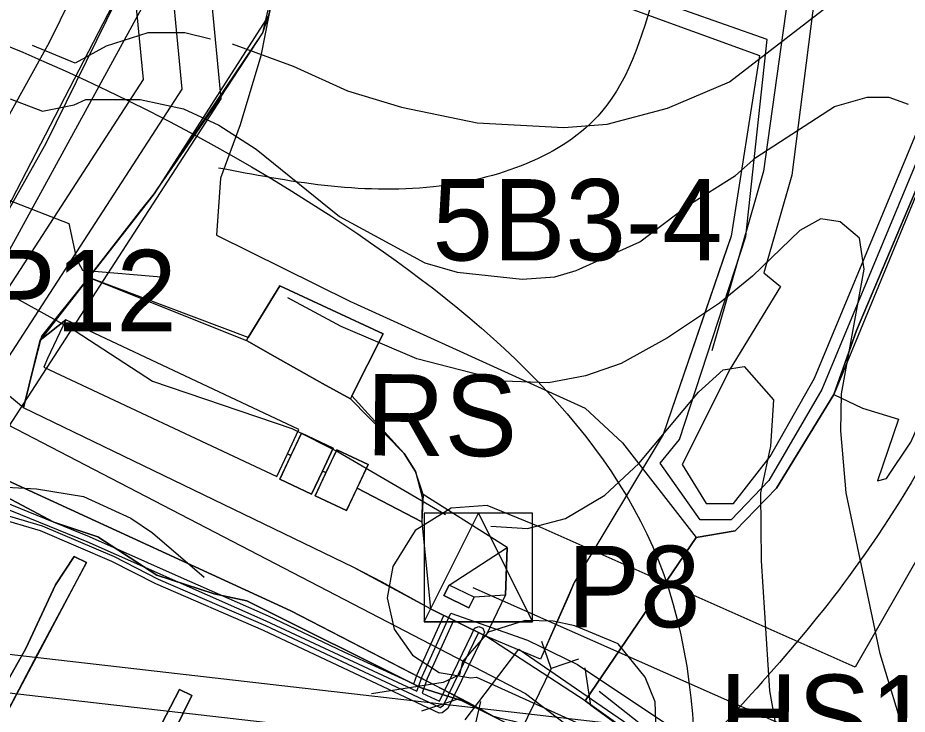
# Model space of a CAD drawing. Extents: x -684583 to -680383, y -1157874 to -1154904.
# Drawn here: x -683041.8 to -682877.8, y -1157026.8 to -1156898.5 of the extents above; entities that cross this region are included whole.
import ezdxf

# ---------------------------------------------------------------- set-up
doc = ezdxf.new("R2010")
doc.units = 0
for name, color, linetype in [('01_DOPRAVA', 7, 'Continuous'), ('01_OBVOD PÚ', 7, 'Continuous'), ('01_VRSTEVNICE', 7, 'Continuous'), ('02_KULTURY NÁVRH', 7, 'Continuous'), ('02_KULTURY STAV', 7, 'Continuous'), ('03_PC_NÁVRH', 7, 'Continuous'), ('03_PC_OBJEKTY_NÁVRH', 7, 'Continuous'), ('03_PC_OBJEKTY_STAV', 7, 'Continuous'), ('03_PC_STAV', 7, 'Continuous'), ('04_ZPF_OP_ORGAN', 7, 'Continuous'), ('06_BIOGEOGRAFIE', 7, 'Continuous'), ('06_ÚSES_IP', 7, 'Continuous'), ('07_ELEKTRO', 7, 'Continuous'), ('07_OCH_P A POPISY TI', 7, 'Continuous'), ('07_PLYNOVOD', 7, 'Continuous'), ('07_VODOVOD', 7, 'Continuous')]:
    doc.layers.add(name, color=color, linetype=linetype)

msp = doc.modelspace()

# ---------------------------------------------------------------- linework, layer by layer
at = {"layer": '01_DOPRAVA'}
msp.add_lwpolyline([(-683054.51, -1157758.92), (-683045.66, -1157702.14), (-683033.32, -1157625.99), (-683033.32, -1157571.3), (-683045.07, -1157508.09), (-683105.62, -1157372.25), (-683148.82, -1157294.04), (-683163.81, -1157254.05), (-683168.81, -1157196.71), (-683165.28, -1157159.67), (-683135.89, -1157075.28), (-683079.46, -1156981.49), (-683035.96, -1156902.98), (-682993.94, -1156817.72), (-682972.78, -1156716.87), (-682952.5, -1156631.31), (-682921.05, -1156497.23), (-682883.43, -1156372.57), (-682870.79, -1156344.34), (-682802.61, -1156200.56), (-682782.62, -1156147.93)], dxfattribs=at)
at = {"layer": '01_OBVOD PÚ'}
for points in [[(-682989.36, -1156869.91), (-682942.73, -1156891.65), (-682905.01, -1156905.43), (-682910.21, -1156938.74), (-682911.04, -1156940.97), (-682922.78, -1156975.26), (-682939.17, -1157002.56), (-682940.26, -1157005.08), (-682945.41, -1157016.69), (-682955.51, -1157012.45), (-682965.71, -1157007.37), (-682974.58, -1157002.46), (-682979.82, -1156999.75), (-683040.73, -1156970.35), (-683038.56, -1156961.55), (-683037.65, -1156957.9), (-683028.68, -1156946.32), (-683018.91, -1156933.75), (-683016.64, -1156930.91), (-682996.6, -1156901.27), (-682995.5, -1156898)], [(-682989.36, -1156869.91), (-682942.73, -1156891.65), (-682905.01, -1156905.43), (-682910.21, -1156938.74), (-682922.78, -1156975.26), (-682939.17, -1157002.56), (-682945.41, -1157016.69), (-682955.51, -1157012.45), (-682965.71, -1157007.37), (-682974.58, -1157002.46), (-682979.82, -1156999.75), (-683040.73, -1156970.35), (-683037.34, -1156957.14), (-683028.68, -1156946.32), (-683018.91, -1156933.75), (-683016.64, -1156930.91), (-683005.44, -1156914.73), (-682996.6, -1156901.27)]]:
    msp.add_lwpolyline(points, close=True, dxfattribs=at)
at = {"layer": '01_VRSTEVNICE'}
for points in [[(-683002.28, -1156903.26), (-682991.01, -1156907.4), (-682981.02, -1156911.96), (-682971.04, -1156914.96), (-682957.06, -1156917.81), (-682941.08, -1156918.67), (-682933.09, -1156918.1), (-682921.97, -1156915.1), (-682910.56, -1156910.25), (-682892.58, -1156896.42)], [(-683006.27, -1156902.41), (-683010.98, -1156901.27), (-683017.83, -1156901.27), (-683025.53, -1156903.69), (-683031.23, -1156906.83), (-683039.08, -1156903.55)], [(-683043.21, -1156913.39), (-683037.22, -1156915.67), (-683031.38, -1156914.53), (-683029.24, -1156913.53), (-683019.25, -1156913.53), (-683011.26, -1156915.25), (-683004.7, -1156918.24), (-682997.85, -1156922.66), (-682982.45, -1156935.07), (-682966.76, -1156943.63), (-682960.77, -1156945.34), (-682948.79, -1156946.63), (-682942.79, -1156946.2), (-682938.8, -1156945.06), (-682927.1, -1156939.78), (-682918.26, -1156933.08), (-682909.42, -1156927.51), (-682905.71, -1156924.23), (-682891.16, -1156914.82), (-682885.17, -1156913.11), (-682881.17, -1156913.11), (-682877.6, -1156914.39)], [(-683053.49, -1156928.23), (-683032.37, -1156936.36), (-683030.95, -1156942.92), (-683029.88, -1156944.95), (-683013.97, -1156946.34)], [(-682877.89, -1157031.64), (-682882.74, -1157015.67), (-682889.02, -1156986), (-682890.01, -1156974.59), (-682889.87, -1156967.74), (-682885.74, -1156944.77), (-682886.59, -1156939.07), (-682890.16, -1156936.07), (-682893.72, -1156935.5), (-682897.58, -1156937.64), (-682906.28, -1156946.06), (-682912.41, -1156951.05), (-682921.97, -1156957.47), (-682930.53, -1156962.18), (-682937.09, -1156964.46), (-682943.93, -1156965.74), (-682952.21, -1156965.46), (-682968.18, -1156961.32), (-682982.16, -1156955.33), (-682992.01, -1156950.05)], [(-683120.37, -1156963.62), (-683111.97, -1156967.03), (-683096.56, -1156967.45), (-683086.86, -1156965.31), (-683079.88, -1156959.75), (-683070.32, -1156948.34), (-683065.75, -1156940.92), (-683060.47, -1156940.92), (-683052.63, -1156944.34), (-683031.23, -1156956.18), (-683016.97, -1156965.46), (-682991.29, -1156974.16), (-682982.73, -1156978.44), (-682962.91, -1156989.99)], [(-682954.57, -1156992.15), (-682947.79, -1156992.56), (-682940.8, -1156990.71), (-682933.52, -1156986.42), (-682927.25, -1156980.58), (-682916.26, -1156967.45), (-682911.7, -1156963.32), (-682907.85, -1156962.75), (-682902.43, -1156968.88), (-682903, -1156977.44), (-682904.85, -1156986), (-682904.71, -1156998.55), (-682903.14, -1157022.51), (-682901, -1157034.5), (-682898.57, -1157042.48), (-682895.15, -1157050.47), (-682887.45, -1157062.46), (-682874.9, -1157079), (-682872.76, -1157083.57), (-682871.9, -1157087.84), (-682870.76, -1157126.36), (-682866.48, -1157156.31), (-682866.48, -1157169.15), (-682867.48, -1157177.43)], [(-683085.58, -1157018.81), (-683075.45, -1157007.39), (-683069.89, -1156996.27), (-683065.47, -1156989.99), (-683056.34, -1156986.42), (-683048.35, -1156984.71), (-683038.36, -1156985.28), (-683029.66, -1156986.71), (-683020.96, -1156990.7), (-683016.95, -1156993.39), (-683007.41, -1157001.54)], [(-682933.95, -1157049.62), (-682930.38, -1157043.48), (-682925.82, -1157038.21), (-682923.96, -1157033.64), (-682924.25, -1157024.51), (-682926.1, -1157019.95), (-682931.1, -1157013.81), (-682939.08, -1157010.53), (-682943.08, -1157009.68), (-682948.21, -1157009.53), (-682955.06, -1157011.67), (-682959.77, -1157017.09), (-682960.34, -1157019.52), (-682963.33, -1157020.95), (-682976.6, -1157023.08)]]:
    msp.add_lwpolyline(points, dxfattribs=at)
at = {"layer": '02_KULTURY NÁVRH'}
msp.add_lwpolyline([(-682862.34, -1156892.05), (-682893.52, -1156966.98), (-682903.32, -1156983.72), (-682910.25, -1156990.96), (-682915.97, -1156990.96), (-682923.35, -1156980.55), (-682919.74, -1156976.18), (-682907.53, -1156938.79), (-682903.62, -1156902.45), (-682942.04, -1156888.88)], dxfattribs=at)
at = {"layer": '02_KULTURY STAV'}
for points in [[(-683056.67, -1156957.12), (-683048.23, -1156942.2), (-683019.85, -1156887.5), (-683003.71, -1156858.2), (-682991.86, -1156824.56), (-682984.3, -1156791.71), (-682974.99, -1156760.13), (-682970.35, -1156763.63), (-682967.31, -1156768.38), (-682966.01, -1156774.58), (-682965.79, -1156787.12), (-682967.42, -1156795.29), (-682979.58, -1156826.78), (-682989.36, -1156869.91), (-682995.5, -1156898), (-683016.64, -1156930.91), (-683028.68, -1156946.32), (-683037.65, -1156957.9), (-683040.73, -1156970.35)], [(-682851.1, -1156826.38), (-682850.89, -1156844.24), (-682854.34, -1156873.25), (-682860.06, -1156892.14), (-682887.1, -1156956.12), (-682891.29, -1156967.88), (-682886.04, -1156970.38), (-682879.39, -1156972.45), (-682883.26, -1156983.81), (-682881.57, -1156983.38), (-682877.08, -1156976.67), (-682874.97, -1156971.91), (-682871.59, -1156959.54), (-682861.19, -1156933.96), (-682850.61, -1156904.16), (-682845.6, -1156883.82), (-682841.06, -1156851.72), (-682842.39, -1156824.87)], [(-682995.5, -1156898), (-682996.97, -1156905.5), (-683000.81, -1156918.21), (-683004.43, -1156928.02), (-683005.16, -1156938.5), (-682980.59, -1156950.71), (-682937.18, -1156970.39), (-682930.27, -1156976.77), (-682916.7, -1156994.23), (-682937.14, -1157024.36), (-682955.51, -1157012.45), (-682951.84, -1157004.88), (-682951.52, -1156996.06), (-682967.04, -1156986.34), (-682968.47, -1156982.08), (-682970.56, -1156978.78), (-682980.18, -1156968.14), (-682974.44, -1156956.7), (-682993.49, -1156947.84), (-682999.31, -1156957.41), (-683028.68, -1156946.32), (-683016.64, -1156930.91), (-682996.6, -1156901.27)], [(-683037.65, -1156957.9), (-683028.68, -1156946.32), (-682999.62, -1156957.92), (-682994.31, -1156960.92), (-682985.63, -1156965.87), (-682980.45, -1156968.68), (-682970.56, -1156978.78), (-682968.47, -1156982.08), (-682967.21, -1156986.78), (-682967.3, -1156991.33), (-682979.24, -1156985.14), (-682977.18, -1156980.78), (-682982.98, -1156978.06), (-682984.97, -1156982.29), (-682985.6, -1156981.99), (-682983.61, -1156977.76), (-682989.5, -1156975), (-682991.45, -1156979.15), (-682992.08, -1156978.85), (-682989.96, -1156974.34), (-683032.95, -1156954.14)], [(-682993.49, -1156947.84), (-682974.44, -1156956.7), (-682980.18, -1156968.14), (-682980.45, -1156968.68), (-682985.63, -1156965.87), (-682994.31, -1156960.92), (-682999.62, -1156957.92), (-682999.31, -1156957.41)], [(-683040.73, -1156970.35), (-683037.65, -1156957.9), (-683032.95, -1156954.14), (-683036.3, -1156961.27), (-683037.02, -1156962.83), (-682994.04, -1156983.03), (-682992.08, -1156978.85), (-682991.45, -1156979.15), (-682993.49, -1156983.51), (-682987.61, -1156986.27), (-682985.6, -1156981.99), (-682984.97, -1156982.29), (-682986.98, -1156986.57), (-682981.19, -1156989.29), (-682979.24, -1156985.14), (-682967.3, -1156991.33), (-682965.71, -1157007.37), (-682979.82, -1156999.75)], [(-683032.95, -1156954.14), (-683036.3, -1156961.27), (-683037.02, -1156962.83), (-682994.04, -1156983.03), (-682992.08, -1156978.85), (-682989.96, -1156974.34)], [(-682989.5, -1156975), (-682983.61, -1156977.76), (-682985.6, -1156981.99), (-682987.61, -1156986.27), (-682993.49, -1156983.51)], [(-682982.98, -1156978.06), (-682977.18, -1156980.78), (-682981.19, -1156989.29), (-682986.98, -1156986.57)], [(-682965.71, -1157007.37), (-682955.51, -1157012.45), (-682951.84, -1157004.88), (-682957.64, -1157005.22), (-682958.64, -1157007.21), (-682963.22, -1157004.92), (-682962.23, -1157003.02), (-682951.52, -1156996.06), (-682967.04, -1156986.34), (-682967.3, -1156991.33)], [(-682962.23, -1157003.02), (-682951.52, -1156996.06), (-682951.84, -1157004.88), (-682957.64, -1157005.22)], [(-682962.23, -1157003.02), (-682963.22, -1157004.92), (-682958.64, -1157007.21), (-682957.64, -1157005.22)]]:
    msp.add_lwpolyline(points, close=True, dxfattribs=at)
for points in [[(-682833.65, -1156897.15), (-682841.03, -1156977.03), (-682844.53, -1157035.81), (-682845.68, -1157065.25), (-682845.68, -1157080.84), (-682844.82, -1157086.77), (-682850.09, -1157090.88), (-682883.77, -1157064.59), (-682922.79, -1157034.61), (-682937.14, -1157024.36), (-682916.7, -1156994.23), (-682909.51, -1156993.03), (-682901.87, -1156985.12), (-682891.29, -1156967.88), (-682886.04, -1156970.38), (-682879.39, -1156972.45), (-682883.26, -1156983.81), (-682881.57, -1156983.38), (-682877.08, -1156976.67), (-682874.97, -1156971.91), (-682871.59, -1156959.54), (-682861.19, -1156933.96), (-682850.61, -1156904.16), (-682845.6, -1156883.82)], [(-683019.85, -1156887.5), (-683036.61, -1156921.65), (-683048.23, -1156942.2)], [(-682995.5, -1156898), (-682996.97, -1156905.5), (-683000.81, -1156918.21), (-683004.43, -1156928.02), (-683005.16, -1156938.5), (-682980.59, -1156950.71), (-682937.18, -1156970.39), (-682930.27, -1156976.77), (-682916.7, -1156994.23), (-682909.51, -1156993.03), (-682901.87, -1156985.12), (-682891.29, -1156967.88), (-682887.1, -1156956.12), (-682860.06, -1156892.14)], [(-682792.27, -1157137.15), (-682805.97, -1157127.99), (-682850.09, -1157090.88), (-682883.77, -1157064.59), (-682922.79, -1157034.61), (-682937.14, -1157024.36), (-682955.51, -1157012.45), (-682965.71, -1157007.37), (-682979.82, -1156999.75), (-683040.73, -1156970.35), (-683056.67, -1156957.12)], [(-683061.29, -1156975.68), (-682991.45, -1157007.74), (-682963.23, -1157022.34), (-682954.24, -1157027.11), (-682953.02, -1157027.48), (-682950.58, -1157028.02), (-682947.67, -1157028.84), (-682927.83, -1157043.62), (-682886.7, -1157076.63), (-682857.33, -1157100.64), (-682818.58, -1157133.57), (-682799.92, -1157147.75), (-682755.75, -1157178.87)], [(-683045.99, -1156985.71), (-683035.15, -1156991.4), (-683027.03, -1156994.1), (-683016.15, -1157001.2), (-683005.6, -1157004.65), (-682999.55, -1157005.9), (-682967.43, -1157021.94), (-682958.63, -1157024.72), (-682991.45, -1157007.74), (-683061.29, -1156975.68)], [(-682954.24, -1157027.11), (-682958.63, -1157024.72), (-682967.43, -1157021.94), (-682999.55, -1157005.9), (-683005.6, -1157004.65), (-683016.15, -1157001.2), (-683027.03, -1156994.1), (-683035.15, -1156991.4), (-683045.99, -1156985.71)], [(-683044.54, -1157047.31), (-683026.78, -1157057.53), (-683003.8, -1157070.41), (-682984.94, -1157081.43), (-682973.97, -1157087.66), (-682964.52, -1157092.89), (-682963.47, -1157089.67), (-682983.84, -1157077.66), (-683002.59, -1157066.71), (-683024.71, -1157053.87), (-683009.7, -1157023.34), (-683011.98, -1157022.24), (-683027.52, -1157052.19), (-683050.51, -1157039.17), (-683029.14, -1156998.86), (-683031.38, -1156997.74), (-683034.85, -1157002.94), (-683040.33, -1157014.68), (-683053.23, -1157037.54)], [(-683053.23, -1157037.54), (-683040.33, -1157014.68), (-683034.85, -1157002.94), (-683031.38, -1156997.74), (-683029.14, -1156998.86), (-683038.16, -1157015.7), (-683050.51, -1157039.17)], [(-683027.52, -1157052.19), (-683011.98, -1157022.24), (-683009.7, -1157023.34), (-683024.71, -1157053.87)]]:
    msp.add_lwpolyline(points, dxfattribs=at)
at = {"layer": '03_PC_NÁVRH'}
msp.add_lwpolyline([(-682964.69, -1156716.62), (-682927.89, -1156728.11), (-682891.83, -1156757.49), (-682882.59, -1156768.47), (-682889.7, -1156822.56), (-682904.3, -1156926.72), (-682913.8, -1156959.84)], dxfattribs=at)
at = {"layer": '03_PC_OBJEKTY_NÁVRH'}
msp.add_lwpolyline([(-682675.61, -1157221.62), (-682750, -1157164.87), (-682805.97, -1157127.99), (-682886.81, -1157060.31), (-682934.61, -1157022.63)], dxfattribs=at)
at = {"layer": '03_PC_OBJEKTY_STAV'}
for points in [[(-682938.42, -1157016.68), (-682943.43, -1157018.4), (-682945.16, -1157013.39)], [(-682943.43, -1157018.4), (-682948.91, -1157029.64)], [(-682921.03, -1157030.03), (-682928.01, -1157031.11), (-682936.09, -1157025.22), (-682937.18, -1157018.23)], [(-682967.28, -1157026.2), (-682960.57, -1157023.98), (-682951.63, -1157028.48), (-682949.42, -1157035.19)]]:
    msp.add_lwpolyline(points, dxfattribs=at)
at = {"layer": '03_PC_STAV'}
for points in [[(-683066.01, -1156961.87), (-682948.18, -1157023.01), (-682876.6, -1157077.37), (-682811.04, -1157131.53), (-682733.64, -1157186.49), (-682671.49, -1157234.52)], [(-682956.44, -1157024.49), (-682963.29, -1157054.08), (-682959.47, -1157076.95), (-682964.05, -1157160.08), (-682974.97, -1157364.97), (-682973.09, -1157394), (-682966.3, -1157425.87), (-682936.61, -1157496.14), (-682917.8, -1157562.99), (-682910.6, -1157586.57), (-682939.66, -1157707.13), (-682946.26, -1157762.29), (-682942.96, -1157791.01), (-682939.8, -1157807.76), (-682935.77, -1157818.43)]]:
    msp.add_lwpolyline(points, dxfattribs=at)
at = {"layer": '04_ZPF_OP_ORGAN'}
msp.add_lwpolyline([(-682878.44, -1156766.12), (-682899.08, -1156927.48), (-682904.19, -1156945.44), (-682901.17, -1156947.96), (-682910.4, -1156963.14), (-682919.29, -1156980.77), (-682914.84, -1156987.98), (-682909.81, -1156987.98), (-682903.02, -1156979.34), (-682894.88, -1156964.91), (-682864.52, -1156891.82)], dxfattribs=at)
at = {"layer": '06_BIOGEOGRAFIE'}
for points in [[(-682820.52, -1156443.86), (-682794.69, -1156436.97), (-682777.47, -1156454.19), (-682792.96, -1156667.78), (-682801.57, -1156726.35), (-682792.96, -1156755.63), (-682811.91, -1156802.14), (-682839.46, -1156886.54), (-682887.67, -1157000.23), (-682920.39, -1157038.12)], [(-683099.47, -1156889.99), (-683108.08, -1156852.09), (-683133.91, -1156841.76), (-683133.91, -1156814.2), (-683132.19, -1156784.91), (-683147.69, -1156747.02), (-683189.01, -1156748.74), (-683242.39, -1156712.57), (-683235.51, -1156631.61), (-683171.79, -1156531.71), (-683097.75, -1156511.04), (-683004.76, -1156526.54), (-682887.67, -1156483.48), (-682868.73, -1156459.36), (-682823.96, -1156452.47), (-682839.46, -1156516.2), (-682863.56, -1156605.77), (-682887.67, -1156736.68), (-682923.83, -1156891.71), (-682934.16, -1156915.82), (-682965.16, -1156929.6), (-683004.76, -1156926.16)], [(-683605.53, -1156693.94), (-683552.15, -1156773.17), (-683505.66, -1156862.74), (-683385.12, -1156876.52), (-683240.48, -1156867.91), (-682983.91, -1156935.09), (-682923.69, -1156998.38), (-682921.97, -1157094.84), (-682923.69, -1157198.19), (-682892.7, -1157272.26), (-682746.33, -1157329.1), (-682572.41, -1157337.72), (-682417.44, -1157289.49), (-682386.73, -1157266.62)], [(-683662.04, -1156787.77), (-683658.6, -1156877.34), (-683631.05, -1156927.29), (-683541.5, -1156975.52), (-683489.85, -1157028.92), (-683414.08, -1157027.2), (-683362.42, -1157025.48), (-683360.7, -1157063.37), (-683464.02, -1157132.27), (-683493.29, -1157163.28), (-683474.35, -1157189.11), (-683407.19, -1157171.89), (-683317.65, -1157115.05), (-683269.44, -1157104.71), (-683207.44, -1157173.61), (-683186.78, -1157259.74), (-683105.85, -1157416.48), (-683069.69, -1157530.17), (-683073.13, -1157580.12), (-683097.24, -1157628.35), (-683264.27, -1157657.63), (-683431.3, -1157647.3), (-683531.17, -1157605.96), (-683636.21, -1157542.23), (-683651.71, -1157521.56), (-683682.7, -1157519.83), (-683708.53, -1157528.45), (-683818.74, -1157547.39), (-683870.4, -1157518.11), (-683980.6, -1157521.56), (-684052.92, -1157490.55), (-684171.74, -1157400.98), (-684213.07, -1157375.14), (-684250.95, -1157388.92), (-684249.23, -1157437.15), (-684237.17, -1157466.44), (-684170.02, -1157518.11), (-684097.7, -1157562.9), (-684011.6, -1157605.96), (-683953.05, -1157602.51), (-683891.06, -1157626.63), (-683835.96, -1157619.74), (-683789.47, -1157599.07), (-683713.7, -1157578.4), (-683625.88, -1157592.18), (-683551.84, -1157667.97), (-683445.07, -1157736.87), (-683346.92, -1157771.32), (-683179.89, -1157767.87), (-683081.74, -1157773.04), (-683016.71, -1157810.65), (-682999.16, -1157844)]]:
    msp.add_spline(points, degree=3, dxfattribs=at)
at = {"layer": '06_ÚSES_IP'}
for points in [[(-683045.5, -1156945.1), (-682993.87, -1156850.83), (-682970.35, -1156763.63), (-682943.14, -1156635.49), (-682907.69, -1156485.87), (-682877.43, -1156403.71), (-682855.81, -1156343.74), (-682797.01, -1156219.49), (-682773.09, -1156158.67), (-682722.07, -1156008.47), (-682663.84, -1155833.77), (-682598.99, -1155629.09), (-682554.6, -1155429.31), (-682533.56, -1155299)], [(-682860.06, -1156892.14), (-682891.29, -1156967.88), (-682901.87, -1156985.12), (-682909.51, -1156993.03), (-682916.7, -1156994.23), (-682937.14, -1157024.36), (-682922.79, -1157034.61), (-682883.77, -1157064.59), (-682851.66, -1157089.7), (-682844.82, -1157086.77), (-682844.53, -1157035.81), (-682841.03, -1156977.03), (-682826.23, -1156835.78)]]:
    msp.add_lwpolyline(points, dxfattribs=at)
at = {"layer": '07_ELEKTRO'}
for points in [[(-683353.35, -1157770.3), (-683109.07, -1157109.08), (-683073.5, -1157019.42), (-683054.68, -1156978.22), (-683011.49, -1156911.63), (-683020.57, -1156816.29), (-682818.44, -1155857.57), (-682314.17, -1155533.82)], [(-683353.35, -1157770.3), (-683109.07, -1157109.08), (-683073.5, -1157019.42), (-683054.68, -1156978.22), (-683011.49, -1156911.63), (-683020.57, -1156816.29), (-682818.44, -1155857.57), (-682314.17, -1155533.82)], [(-683109.85, -1156972.97), (-683108.82, -1156972), (-683106.99, -1156971.32), (-683096.35, -1156974.37), (-683089.84, -1156976.71), (-683076.02, -1156983.39), (-683069.94, -1156985.35), (-683061.72, -1156987.44), (-683055.3, -1156988.34), (-683050.05, -1156988.34), (-683037.29, -1156992.08), (-683024.04, -1156997.74), (-683015.94, -1157001.9), (-682996.1, -1157010.47), (-682963.9, -1157025.6), (-682963.28, -1157025.13), (-682956.8, -1157011.7)], [(-683073.5, -1157019.42), (-682902.81, -1157038.95), (-682625.19, -1157075.68)]]:
    msp.add_lwpolyline(points, dxfattribs=at)
at = {"layer": '07_OCH_P A POPISY TI'}
for p, q in [((-683027.64, -1156815.89), (-683018.69, -1156909.87)), ((-683004.29, -1156913.39), (-683013.5, -1156816.69)), ((-683018.69, -1156909.87), (-683060.83, -1156974.84)), ((-683048.53, -1156981.6), (-683004.29, -1156913.39)), ((-683044.63, -1156987.57), (-683028.67, -1156994.03)), ((-683037.63, -1156993.02), (-683050.19, -1156989.34)), ((-682961.89, -1156988.83), (-682968.52, -1156992.97)), ((-682955.25, -1156988.36), (-682961.89, -1156988.83)), ((-682945.46, -1156992.34), (-682955.25, -1156988.36)), ((-682887.34, -1157018.11), (-682945.46, -1156992.34)), ((-683024.47, -1156998.65), (-683037.63, -1156993.02)), ((-683028.67, -1156994.03), (-683012.24, -1157001.36)), ((-682968.52, -1156992.97), (-682972.66, -1156999.58)), ((-682874.5, -1156995.7), (-682887.34, -1157018.11)), ((-683016.37, -1157002.8), (-683024.47, -1156998.65)), ((-682972.66, -1156999.58), (-682973.68, -1157005.37)), ((-683012.24, -1157001.36), (-682995.61, -1157008.67)), ((-682996.51, -1157011.38), (-683016.37, -1157002.8)), ((-682973.68, -1157005.37), (-682972.4, -1157011.11)), ((-682995.61, -1157008.67), (-682981.7, -1157015.32)), ((-682968.15, -1157019.48), (-682963.22, -1157008.6)), ((-682961.4, -1157009.42), (-682966.29, -1157020.22)), ((-682958.04, -1157012.07), (-682957.56, -1157010.93)), ((-682957.56, -1157010.93), (-682956.79, -1157010.62)), ((-682956.79, -1157010.62), (-682956.03, -1157010.94)), ((-682956.03, -1157010.94), (-682955.72, -1157011.71)), ((-682977.53, -1157020.27), (-682996.51, -1157011.38)), ((-682972.4, -1157011.11), (-682969.03, -1157015.93)), ((-682964.05, -1157024.43), (-682958.04, -1157012.07)), ((-682955.72, -1157011.71), (-682956.22, -1157012.89)), ((-682901.95, -1157032), (-683063.13, -1157013.56)), ((-682956.22, -1157012.89), (-682962.49, -1157025.78)), ((-682981.7, -1157015.32), (-682968.76, -1157021.22)), ((-682969.03, -1157015.93), (-682964.07, -1157019.09)), ((-682964.07, -1157019.09), (-682958.28, -1157020.11)), ((-682964.07, -1157026.62), (-682977.53, -1157020.27)), ((-682968.76, -1157021.22), (-682968.15, -1157019.48)), ((-682966.29, -1157020.22), (-682967.2, -1157022.93)), ((-682958.28, -1157020.11), (-682957.22, -1157019.98)), ((-682957.22, -1157019.98), (-682921.25, -1157036.19)), ((-682967.2, -1157022.93), (-682964.05, -1157024.43)), ((-682963.52, -1157026.57), (-682964.07, -1157026.62)), ((-682962.49, -1157025.78), (-682963.52, -1157026.57))]:
    msp.add_line(p, q, dxfattribs=at)
at = {"layer": '07_PLYNOVOD'}
for points in [[(-683147.01, -1156952.11), (-683137.67, -1156959.94), (-683133.31, -1156965.24), (-683117.07, -1156969.63), (-683111.6, -1156967.36), (-683104.51, -1156969.61), (-683100.04, -1156971.88), (-683094.9, -1156975.24), (-683072.81, -1156986.32), (-683066.71, -1156988.26), (-683055.41, -1156989.46), (-683050.72, -1156987.03), (-683044.94, -1156988.52), (-683029.06, -1156994.95), (-682996.03, -1157009.58), (-682968.18, -1157022.59), (-682967.22, -1157019.85), (-682961.95, -1157008.21), (-682947.77, -1157013.15), (-682938.57, -1157017.66), (-682845.48, -1157079.73), (-682740.19, -1157153.94), (-682703.61, -1157187.85), (-682654.74, -1157227.72)], [(-682882.73, -1157052.19), (-682892.85, -1157046.94), (-682891.62, -1157032.79), (-682957.83, -1157003.5)]]:
    msp.add_lwpolyline(points, dxfattribs=at)
for points in [[(-682966.85, -1157009.76), (-682946.85, -1157009.76), (-682946.85, -1156989.76), (-682966.85, -1156989.76)], [(-682966.85, -1157009.76), (-682956.85, -1156989.76), (-682946.85, -1157009.76)]]:
    msp.add_lwpolyline(points, close=True, dxfattribs=at)
at = {"layer": '07_VODOVOD'}
msp.add_lwpolyline([(-682959.31, -1157027.82), (-682949.41, -1157014.81), (-682795.34, -1157120.72), (-682713.54, -1157183.93), (-682627.78, -1157260.58)], dxfattribs=at)

# ---------------------------------------------------------------- texts
at = {"layer": '03_PC_OBJEKTY_STAV'}
for s, p in [('P12', (-683048.16, -1156956.24)), ('P8', (-682940.42, -1157010.78))]:
    msp.add_text(s, height=15, dxfattribs=at).set_placement(p)
msp.add_text('HS14', height=15, rotation=359.597, dxfattribs=at).set_placement((-682912.51, -1157034.37))
at = {"layer": '06_BIOGEOGRAFIE'}
msp.add_text('5B3-4', height=15, dxfattribs=at).set_placement((-682965.33, -1156943.19))
at = {"layer": '07_OCH_P A POPISY TI'}
msp.add_text('RS', height=15, rotation=359.5994, dxfattribs=at).set_placement((-682977.61, -1156979.11))

doc.saveas('drawing.dxf')
